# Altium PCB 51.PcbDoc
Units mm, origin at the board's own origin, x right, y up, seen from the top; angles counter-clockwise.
Board outline 100 x 100 mm, 2 copper layers (Top Layer, Bottom Layer); 85 components, 82 nets, 374 pads, 113 vias.
Unrouted connection lines stored in the file: 45.
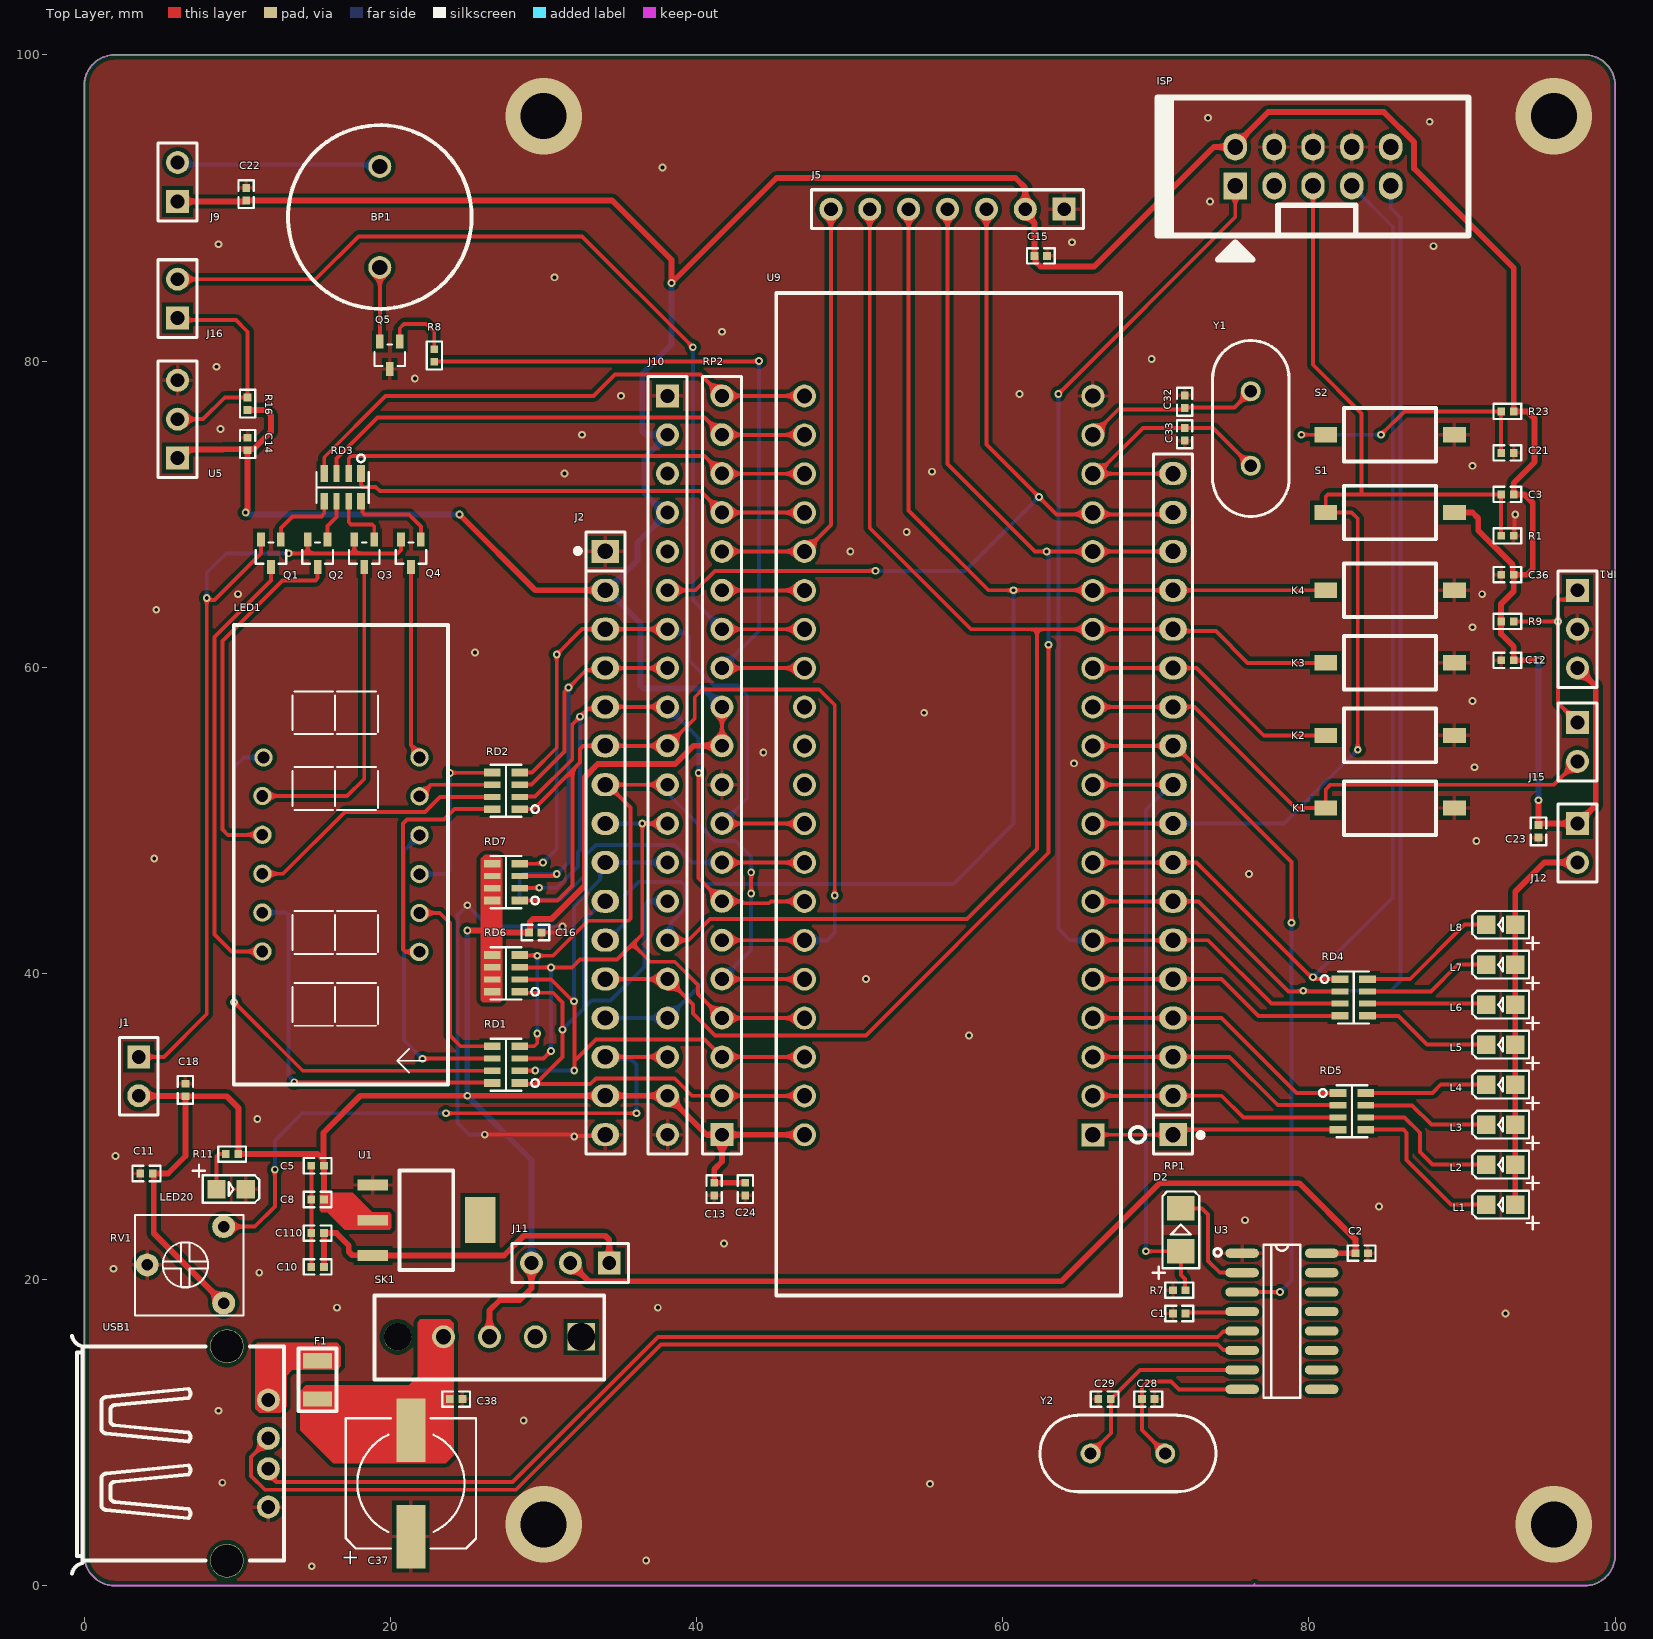
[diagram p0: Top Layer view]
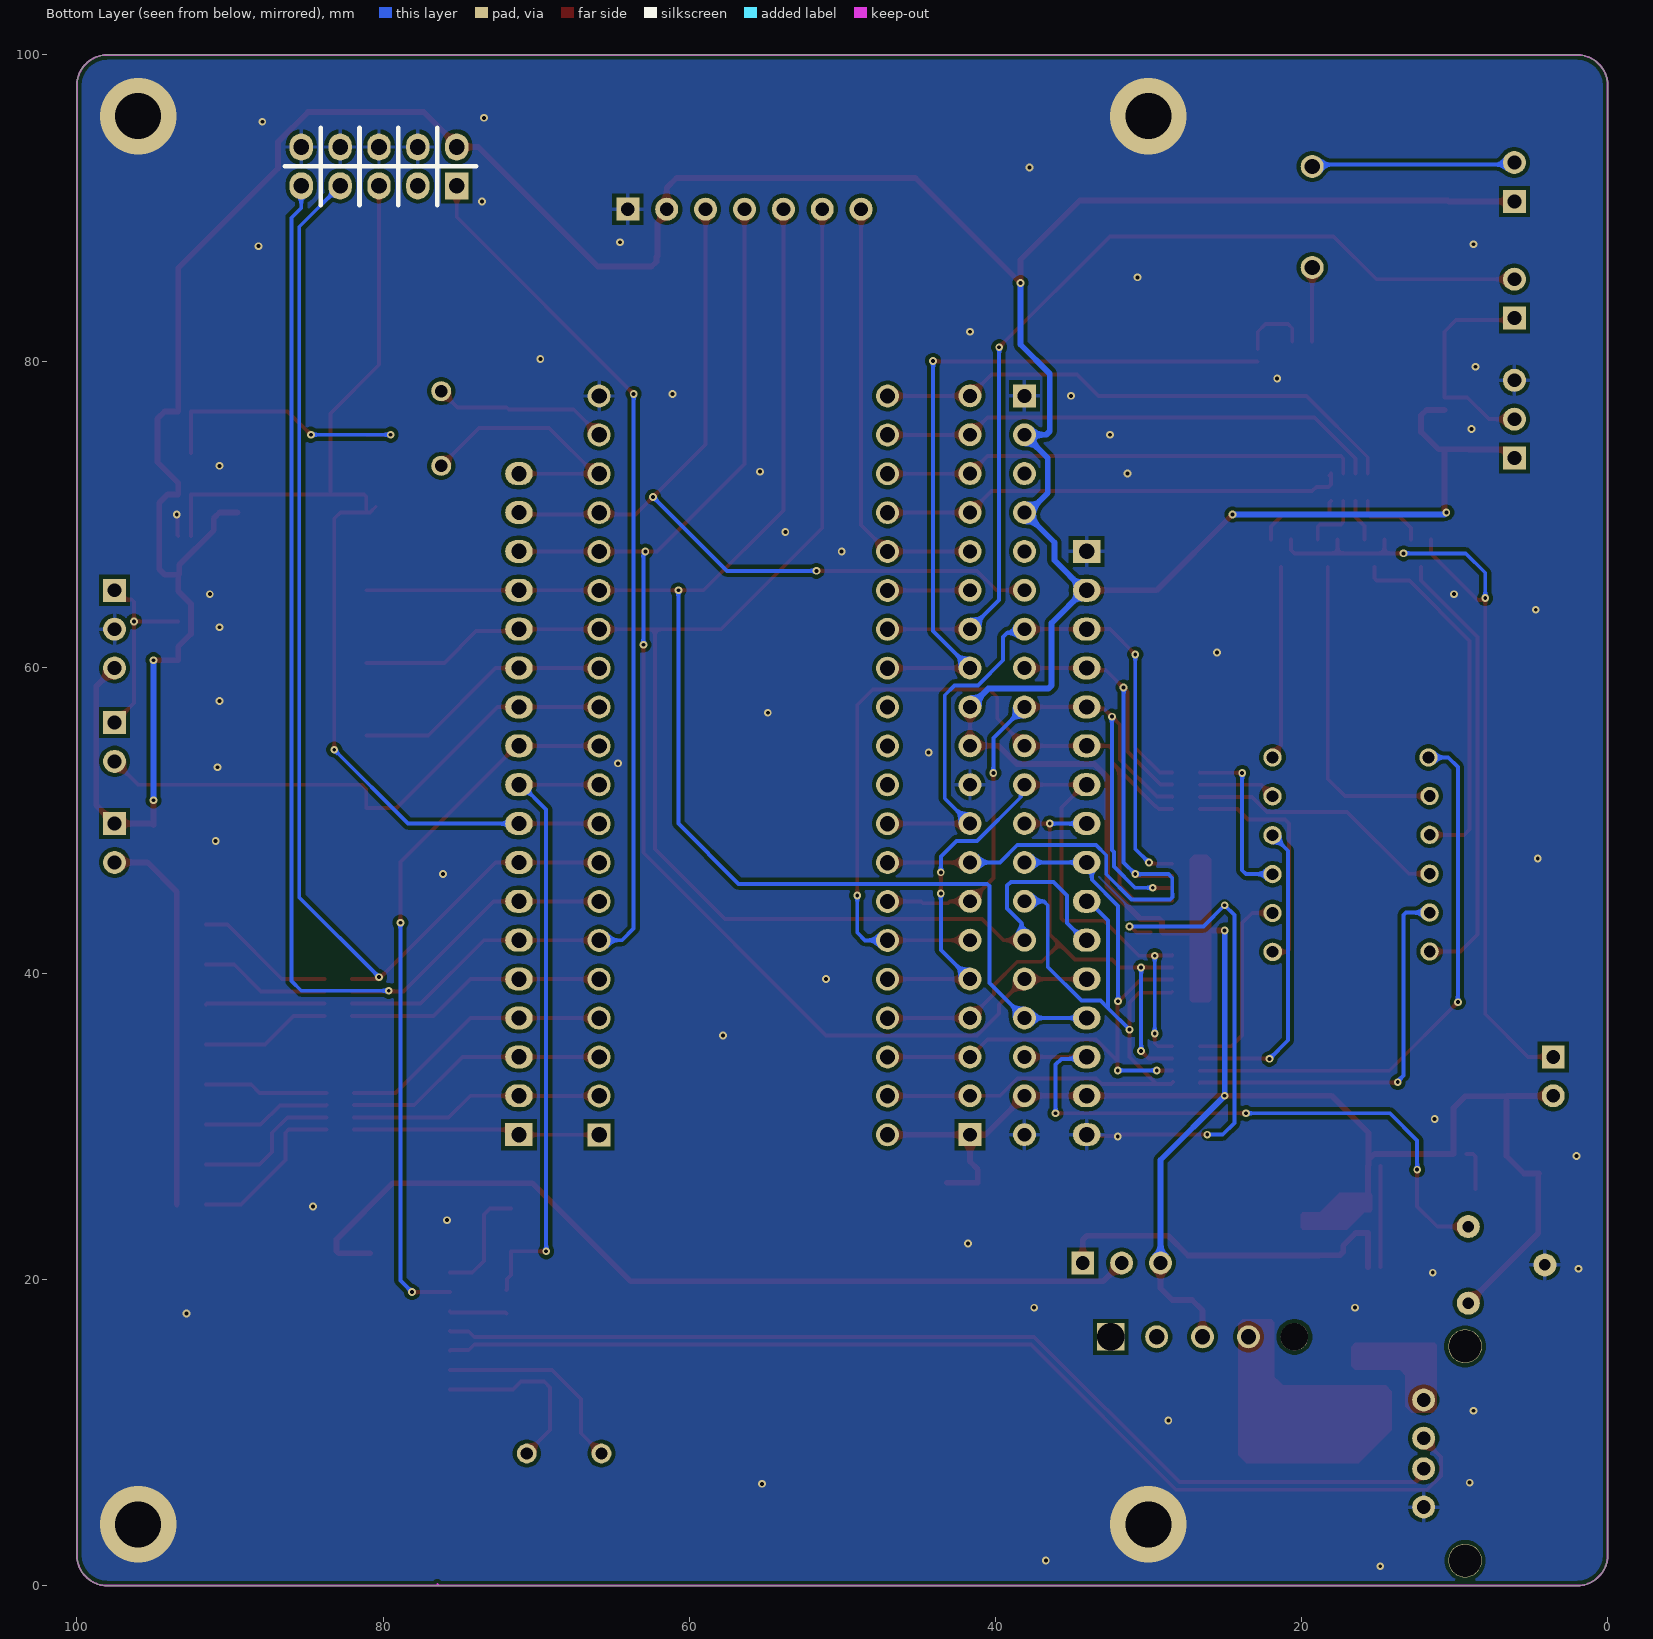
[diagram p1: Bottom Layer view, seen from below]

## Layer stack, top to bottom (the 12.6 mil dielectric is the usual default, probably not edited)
Top Solder: solder mask 0.0102, Solder Resist, Dk 3.5
Top Layer: signal copper 0.0356
Dielectric 1: dielectric 0.32, FR-4, Dk 4.8
Bottom Layer: signal copper 0.0356
Bottom Solder: solder mask 0.0102, Solder Resist, Dk 3.5

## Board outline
2,0 cw(c2,2) 0,2 0,98 cw(c2,98) 2,100 98,100 cw(c98,98) 100,98 100,2 cw(c98,2) 98,0

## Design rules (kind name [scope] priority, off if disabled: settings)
Clearance [All] p1: gap=0.254 ignorepadtopadclearanceinfootprint=FALSE
ComponentClearance [All] p1: gap=0.254 collisioncheckmode=3 verticalgap=100 showdistances=TRUE donotcheckwithout3dbody=TRUE checkcomponentboundary=TRUE
DiffPairsRouting DiffPair_USBDiffPairsRouting [InDifferentialPair ('D_D')] p1: maxlimit=0.254 minlimit=0.254 mostfreqgap=0.254 toplayer_minwidth=0.127 toplayer_maxwidth=0.381 toplayer_prefwidth=0.254 bottomlayer_minwidth=0.127 bottomlayer_maxwidth=0.381 bottomlayer_prefwidth=0.254 maxuncoupledlength=12.7
DiffPairsRouting [All] p2: maxlimit=0.254 minlimit=0.254 mostfreqgap=0.254 toplayer_minwidth=0.381 toplayer_maxwidth=0.381 toplayer_prefwidth=0.381 bottomlayer_minwidth=0.381 bottomlayer_maxwidth=0.381 bottomlayer_prefwidth=0.381 maxuncoupledlength=12.7
Height [All] p1: minheight=-200 maxheight=200 prefheight=26.142
MatchedLengths DiffPair_USBMatchedLengths [InDifferentialPair ('D_D')] p1: tolerance=25.4 checknetsindiffpair=TRUE checkdiffpairvsdiffpair=FALSE checkxsignals=FALSE checkothers=FALSE
MinimumSolderMaskSliver [All] p1: minsoldermaskwidth=0.025
PlaneClearance [All] p1: clearance=0.203
PlaneConnect [All] p1: pad.planeconnectstyle=Relief pad.reliefexpansion=0.508 pad.reliefentries=4 pad.reliefconductorwidth=0.254 pad.reliefairgap=0.254 via.planeconnectstyle=Direct via.reliefexpansion=0.508 via.reliefentries=4 via.reliefconductorwidth=0.254 via.reliefairgap=0.254
PolygonConnect [All] p1: thpad.connectstyle=Relief thpad.reliefconductorwidth=0.254 thpad.reliefentries=4 thpad.polygonreliefangle="90 Angle" thpad.airgapwidth=0.254 smdpad.connectstyle=Relief smdpad.reliefconductorwidth=0.254 smdpad.reliefentries=4 smdpad.polygonreliefangle="90 Angle" smdpad.airgapwidth=0.254 via.connectstyle=Direct via.reliefconductorwidth=0.254 via.reliefentries=4 via.polygonreliefangle="90 Angle" via.airgapwidth=0.254
RoutingVias [All] p1: holewidth=0.254 width=0.508 viastyle="Through Hole" minholewidth=0.254 minwidth=0.508 maxholewidth=0.254 maxwidth=0.508
SilkToSilkClearance [All] p1: silktosilkclearance=0.025
SilkToSolderMaskClearance [IsPad] p1: minsilkscreentomaskgap=0.025 clearancetoexposedcopper=TRUE
SolderMaskExpansion [All] p1: expansion=0.102 istentingtop=FALSE
SupplyNets "Schematic Supply Nets_3" [InNet('GND')] p1: voltage=0.000
SupplyNets "Schematic Supply Nets_2" [InNet('VCC')] p2: voltage=0.000
SupplyNets "Schematic Supply Nets_1" [InNet('VCC_CPU')] p3: voltage=0.000
SupplyNets "Schematic Supply Nets" [InNet('3.3V')] p4: voltage=0.000
Width Width_power [InNetClass('Power')] p1: maxlimit=2.54 minlimit=0.203 preferedwidth=0.381
Width [InNetClass('All Nets')] p2: maxlimit=2.032 minlimit=0.102 preferedwidth=0.254
22 further rules are at their usual default settings.

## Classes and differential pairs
net class Power: 3.3V NetJ12_2 VCC VCC_CPU
differential pair D_D: +D+ -D-

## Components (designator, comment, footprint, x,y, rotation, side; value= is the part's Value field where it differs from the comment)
BP1 "BUZZER" BUZZER 19.304,89.408 r270 top
C1 "104" FPC-0402C 71.53,17.78 r0 top
C2 "104" FPC-0402C 83.439,21.717 r180 top
C3 "105" FPC-0402C 92.964,71.289 r0 top
C5 "220uF/16V" FPC-0402C 15.24,27.432 r0 top
C8 "104" FPC-0402C 15.24,25.231 r0 top
C10 "104" FPC-0402C 15.24,20.828 r0 top
C11 "104" FPC-0402C 4.064,26.924 r0 top
C12 "104" FPC-0402C 92.964,60.452 r0 top
C13 "104" FPC-0402C 41.148,25.908 r90 top
C14 "104" FPC-0402C 10.668,74.578 r270 top
C15 "104" FPC-0402C 62.484,86.868 r180 top
C16 "104" FPC-0402C 29.464,42.672 r180 top
C18 "104" FPC-0402C 6.604,32.385 r270 top
C21 "105" FPC-0402C 92.964,73.999 r180 top
C22 "104" FPC-0402C 10.578,90.902 r270 top
C23 "104" FPC-0402C 94.996,49.276 r90 top
C24 "104" FPC-0402C 43.18,25.908 r90 top
C28 "20P" FPC-0402C 69.498,12.192 r0 top
C29 "20P" FPC-0402C 66.646,12.192 r180 top
C32 "30pF" FPC-0402C 71.882,77.343 r270 top
C33 "30pF" FPC-0402C 71.882,75.213 r90 top
C36 "102" FPC-0402C 92.964,66.04 r0 top
C37 "100uF/16V" FPC-CPCSM-3R2X8R0-1 21.336,6.685 r90 top
C38 "104" FPC-0402C 24.286,12.192 r0 top
C110 "10uF/10V" FPC-0402C 15.24,23.029 r180 top
D2 "1N4148" FPC-1206D 71.628,23.244 r90 top
F1 "FUSE" 1206F 15.24,12.192 r90 top
IR1 "IRRED" HDR1X3 97.536,65.024 r270 top
ISP "ISP" IDE-10 80.264,92.71 r0 top
J1 "2PIN排针" HDR1X2 3.556,34.544 r270 top
J2 "LCD-1602" HDR1X16 34.036,48.514 r270 top
J5 "SIP7" HDR1X7 64.008,89.916 r180 top
J9 "J9" HDR1X2 6.096,90.424 r90 top
J10 "LCD128-64" HDR1X20 38.1,77.724 r270 top
J11 "SIP3" HDR1X3 34.29,21.082 r180 top
J12 "CON2" HDR1X2 97.536,49.784 r270 top
J15 "CON2" HDR1X2 97.536,56.388 r270 top
J16 "CON2" HDR1X2 6.096,82.804 r90 top
K1 "SW-PB" SW-PB 82.296,50.8 r180 top
K2 "SW-PB" SW-PB 82.296,55.541 r180 top
K3 "SW-PB" SW-PB 82.296,60.283 r180 top
K4 "SW-PB" SW-PB 82.296,65.024 r180 top
L1 "LED" FPC-0805D 92.522,24.892 r180 top
L2 "LED" FPC-0805D 92.522,27.505 r180 top
L3 "LED" FPC-0805D 92.522,30.117 r180 top
L4 "LED" FPC-0805D 92.522,32.73 r180 top
L5 "LED" FPC-0805D 92.522,35.342 r180 top
L6 "LED" FPC-0805D 92.522,37.955 r180 top
L7 "LED" FPC-0805D 92.522,40.567 r180 top
L8 "LED" FPC-0805D 92.522,43.18 r180 top
LED1 "4连数码管" CL3641A 16.764,47.752 r90 top
LED20 "RED" FPC-0805D 9.586,25.908 r0 top
Q1 "PNP三极管" FPC-SOT323 12.192,67.448 r180 top
Q2 "PNP三极管" FPC-SOT323 15.24,67.448 r180 top
Q3 "PNP三极管" FPC-SOT323 18.288,67.448 r180 top
Q4 "PNP三极管" FPC-SOT323 21.336,67.448 r180 top
Q5 "PNP三极管" FPC-SOT323 19.954,80.38 r180 top
R1 "10K" FPC-0402R 92.964,68.58 r180 top
R7 "10K" FPC-0402R 71.53,19.304 r0 top
R8 "1K" FPC-0402R 22.86,80.362 r90 top
R9 "5.1K" FPC-0402R 92.964,62.992 r180 top
R11 "1K" FPC-0402R 9.652,28.194 r0 top
R16 "5.1K" FPC-0402R 10.668,77.216 r270 top
R23 "10K" FPC-0402R 92.964,76.708 r0 top
RD1 "100*4" FPC-0603RA 27.548,34.036 r90 top
RD2 "100*4" FPC-0603RA 27.548,51.924 r90 top
RD3 "1k*4" FPC-0603RA 16.872,71.744 r180 top
RD4 "1K*4" FPC-0603RA 82.92,38.424 r270 top
RD5 "1K*4" FPC-0603RA 82.804,30.988 r270 top
RD6 "10K*4" FPC-0603RA 27.548,39.999 r90 top
RD7 "10K*4" FPC-0603RA 27.548,45.961 r90 top
RP1 "18PIN" HDR1X18 71.12,51.054 r90 top
RP2 "20PIN" HDR1X20 41.656,29.464 r90 top
RV1 "10K" RV 6.604,20.955 r90 top
S1 "RST" SW-PB 82.296,70.104 r180 top
S2 "RST" SW-PB 82.296,75.184 r180 top
SK1 "滑动开关" SS-12F44 26.464,16.256 r180 top
U1 "IC_LM1117" SOP-223-3L 22.352,23.876 r270 top
U3 "IC_CH340G" FPC-SO16-150 78.232,17.272 r270 top
U5 "18B20" HDR1X3 6.096,73.66 r90 top
U9 "IC_AT89C5122D-RDRU" DIP40 78.583,26.915 r90 top
USB1 "TYPEC" USB_A 10.668,8.636 r270 top
Y1 "11.0592M" FPC-CO2-5R0X11R5-V 76.2,73.152 r90 top
Y2 "12M" FPC-CO2-5R0X11R5-V 70.612,8.636 r180 top

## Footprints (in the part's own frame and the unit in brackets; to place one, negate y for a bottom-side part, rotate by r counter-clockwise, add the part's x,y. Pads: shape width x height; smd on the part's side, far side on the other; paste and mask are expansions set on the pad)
1206F [mm]
  rect 1x1.9 smd: 1(0,0) 2(2.5,0)
  silkscreen extent -0.8,-1.23 3.3,1.25, body extent -0.33,-0.8 2.87,0.8, height 0.55
BUZZER [mm]
  round 1.5 hole 1: 1(-3.3,0) 2(3.3,0)
  silkscreen extent -6,-6 6,6, body extent -5.87,-5.99 6.13,5.99, height 9
CL3641A [mm]
  round 1.2 hole 0.65: 1(-6.352,-5.101)
  round 1.2 hole 0.762: 1(-6.348,-5.132) 1(-6.348,-5.132) 2(-3.808,-5.132) 3(-1.268,-5.132) 4(1.272,-5.132) 5(3.812,-5.132) 6(6.352,-5.132) 7(6.348,5.059) 8(3.837,5.132) 9(1.297,5.132) 10(-1.243,5.132) 11(-3.783,5.132) 12(-6.323,5.132)
  silkscreen extent -15,-7 15,7, body extent -14.73,-7.25 15.27,6.75, height 2
DIP40 [mm]
  rect 1.5x1.5 hole 1: 1(2.54,12.7)
  round 1.5 hole 1: 2(5.08,12.7) 3(7.62,12.7) 4(10.16,12.7) 5(12.7,12.7) 6(15.24,12.7) 7(17.78,12.7) 8(20.32,12.7) 9(22.86,12.7) 10(25.4,12.7) 11(27.94,12.7) 12(30.48,12.7) 13(33.02,12.7) 14(35.56,12.7) 15(38.1,12.7) 16(40.64,12.7) 17(43.18,12.7) 18(45.72,12.7) 19(48.26,12.7) 20(50.8,12.7) 21(50.8,31.54) 21(50.8,31.54) 22(48.26,31.54) 23(45.72,31.54) 24(43.18,31.54) 25(40.64,31.54) 26(38.1,31.54) 27(35.56,31.54) 28(33.02,31.54) 29(30.48,31.54) 30(27.94,31.54) 31(25.4,31.54) 32(22.86,31.54) 33(20.32,31.54) 34(17.78,31.54) 35(15.24,31.54) 36(12.7,31.54) 37(10.16,31.54) 38(7.62,31.54) 39(5.08,31.54) 40(2.54,31.54)
  silkscreen extent -7.96,9.27 57.54,33.38, body extent -8.11,10.07 57.39,34.13, height 26.14
FPC-0402C [mm]
  rect 0.51x0.51 smd: 1(-0.41,0) 2(0.41,0)
  silkscreen extent -0.91,-0.5 0.91,0.5
FPC-0402R [mm]
  rect 0.51x0.51 smd: 1(-0.41,0) 2(0.41,0)
  silkscreen extent -0.91,-0.5 0.91,0.5
FPC-0603RA [mm]
  rect 0.5x1.1 smd: 1(-1.2,-0.9) 4(1.2,-0.9) 5(1.2,0.9) 8(-1.2,0.9)
  rect 0.4x1.1 smd: 2(-0.4,-0.9) 3(0.4,-0.9) 6(0.4,0.9) 7(-0.4,0.9)
  silkscreen extent -1.7,-2.15 1.7,1
FPC-0805D [mm]
  rect 1.2x1.2 smd: 1(0.95,0) 2(-0.95,0)
  silkscreen extent -2.5,-0.9 1.85,1.6
FPC-1206D [mm]
  rect 1.6x1.8 smd: 1(-1.4,0) 2(1.4,0)
  silkscreen extent -3.2,-1.2 2.5,1.85
FPC-CO2-5R0X11R5-V [mm]
  round 1.3 hole 0.8: 1(0,0) 2(4.88,0)
  silkscreen extent -3.31,-2.5 8.19,2.5
FPC-CPCSM-3R2X8R0-1 [mm]
  rect 4.15x1.9 smd: 1(-3.475,0) 2(3.475,0)
  silkscreen extent -4.25,-4.25 4.25,4.25
FPC-SO16-150 [mm]
  oval 0.6x2.2 smd: 1(-4.445,-2.6) 2(-3.175,-2.6) 3(-1.905,-2.6) 4(-0.635,-2.6) 5(0.635,-2.6) 6(1.905,-2.6) 7(3.175,-2.6) 8(4.445,-2.6) 9(4.445,2.6) 10(3.175,2.6) 11(1.905,2.6) 12(0.635,2.6) 13(-0.635,2.6) 14(-1.905,2.6) 15(-3.175,2.6) 16(-4.445,2.6)
  silkscreen extent -5,-4.45 5,1.2
FPC-SOT323 [mm]
  rect 0.5x0.9 smd: 1(-0.65,-0.9) 2(0.65,-0.9) 3(0,0.9)
  silkscreen extent -1,-0.7 1,0.7
HDR1X2 [mm] "Connector; Header; 2 Position"
  rect 1.5x1.5 hole 0.9: 1(0,0)
  round 1.5 hole 0.9: 2(2.54,0)
  silkscreen extent -1.27,-1.27 3.81,1.27, body extent -1.29,-1.37 3.79,1.17, height 8.43
HDR1X3 [mm] "Connector; Header; 3 Position"
  rect 1.5x1.5 hole 0.9: 1(0,0)
  round 1.5 hole 0.9: 2(2.54,0) 3(5.08,0)
  silkscreen extent -1.27,-1.27 6.35,1.27, body extent -1.27,-1.27 6.35,1.27, height 8
HDR1X7 [mm] "Connector; Header; 7 Position"
  rect 1.5x1.5 hole 0.9: 1(0,0)
  round 1.5 hole 0.9: 2(2.54,0) 3(5.08,0) 4(7.62,0) 5(10.16,0) 6(12.7,0) 7(15.24,0)
  silkscreen extent -1.27,-1.27 16.51,1.27, body extent -1.27,-1.27 16.51,1.27, height 8.54
HDR1X16 [mm] "ZLGLIB"
  rect 1.5x1.8 hole 1: 1(-19.05,0)
  oval 1.5x1.8 hole 1: 2(-16.51,0) 3(-13.97,0) 4(-11.43,0) 5(-8.89,0) 6(-6.35,0) 7(-3.81,0) 8(-1.27,0) 9(1.27,0) 10(3.81,0) 11(6.35,0) 12(8.89,0) 13(11.43,0) 14(13.97,0) 15(16.51,0) 16(19.05,0)
  silkscreen extent -20.32,-1.92 20.32,1.27, body extent -20.32,-1.27 20.32,1.27, height 7.58
HDR1X18 [mm] "ZLGLIB"
  rect 1.5x1.8 hole 1: 1(-21.59,0)
  oval 1.5x1.8 hole 1: 2(-19.05,0) 3(-16.51,0) 4(-13.97,0) 5(-11.43,0) 6(-8.89,0) 7(-6.35,0) 8(-3.81,0) 9(-1.27,0) 10(1.27,0) 11(3.81,0) 12(6.35,0) 13(8.89,0) 14(11.43,0) 15(13.97,0) 16(16.51,0) 17(19.05,0) 18(21.59,0)
  silkscreen extent -22.86,-1.92 22.86,1.27, body extent -22.86,-1.27 22.86,1.27, height 7.58
HDR1X20 [mm] "Connector; Header; 20 Position"
  rect 1.5x1.5 hole 0.9: 1(0,0)
  round 1.5 hole 0.9: 2(2.54,0) 3(5.08,0) 4(7.62,0) 5(10.16,0) 6(12.7,0) 7(15.24,0) 8(17.78,0) 9(20.32,0) 10(22.86,0) 11(25.4,0) 12(27.94,0) 13(30.48,0) 14(33.02,0) 15(35.56,0) 16(38.1,0) 17(40.64,0) 18(43.18,0) 19(45.72,0) 20(48.26,0)
  silkscreen extent -1.27,-1.27 49.53,1.27, body extent -1.34,-1.41 49.46,1.13, height 7.36
IDE-10 [mil] "IDC-10-B,ZLGLIB"
  rect 60x70 hole 40: 1(-200,-50)
  oval 60x70 hole 40: 2(-200,50) 3(-100,-50) 4(-100,50) 5(0,-50) 6(0,50) 7(100,-50) 8(100,50) 9(200,-50) 10(200,50)
  silkscreen extent -400,-240 400,177, body extent -400,-175 400,175, height 394
RV [mm]
  round 1.5 hole 0.762: 1(-2.5,-2.5) 2(0,2.5) 3(2.5,-2.5)
  silkscreen extent -3.3,-3.8 3.26,3.3, body extent -3.2,-3.8 3.2,3.2, height 7.5
SOP-223-3L [mm]
  rect 0.7x2 smd: 1(-2.3,-3.5) 2(0,-3.5) 3(2.3,-3.5)
  rect 3x2 smd: 4(0,3.5)
  silkscreen extent -3.25,-1.75 3.25,1.75, body extent -3.25,-3.63 3.25,3.37, height 0.89
SS-12F44 [mm]
  round 1.5 hole 1: 1(-3,0) 2(0,0) 3(3,0)
  rect 1.8x1.8 hole 1.8: 4(-6,0)
  round 1.8 hole 1.8: 5(6,0)
  silkscreen extent -7.5,-2.71 7.5,2.79, body extent -5.97,-2.88 6.23,2.92, height 11.75
SW-PB [mm]
  rect 1.5x1 smd: 1(-7.2,0) 2(1.2,0)
  silkscreen extent -6,-1.75 0,1.75, body extent -7.03,-1.7 0.97,1.8, height 2.59
USB_A [mm]
  round 1.5 hole 0.9: 1(-3.5,1.355) 2(-1,1.355) 3(1,1.355) 4(3.5,1.355)
  round 2.2 hole 2.1: GND(-7,-1.355) GND(7,-1.355)
  silkscreen extent -7.68,-11.47 7.85,2.37, body extent -7.75,-11.88 8.05,2.22, height 6.35

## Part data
C1 C2 C3 C5 C8 C10 C11 C12 C13 C14 C15 C16 C18 C21 C22 C23 C24 C28 C29 C32 C33 C36 C37 C38: library part CAP
C110: library part CAP1
D2: library part 二极管
IR1 U5: library part SIP3
ISP: library part IC_ISP
J2: library part 16PIN
J9 J12 J15 J16: library part 2PIN排针
J10: library part 20PIN
K1 K2 K3 K4 S1 S2: library part KEY
LED20: library part LED
R1 R7 R8 R9 R11 R16 R23: library part res1
RD1 RD2 RD3 RD4 RD5 RD6 RD7: library part RP
RV1: library part VR
USB1: library part USB座
Y1 Y2: library part XT

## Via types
v1: diameter 0.508, hole 0.254, Top Layer to Bottom Layer, 109 vias
v2: diameter 5, hole 3, Top Layer to Bottom Layer, 4 vias

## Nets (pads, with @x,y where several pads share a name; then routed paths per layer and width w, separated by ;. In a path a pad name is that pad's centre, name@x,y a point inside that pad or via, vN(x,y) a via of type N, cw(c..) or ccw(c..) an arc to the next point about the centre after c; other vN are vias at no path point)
3.3V: C10.2 C110.1 J11.1 U1.3 | length 23.8
  Top Layer w0.381: C10.2 C110.1 16.468,23.029 17.272,22.225 17.272,21.813 17.495,21.59 18.838,21.59 U1.3 27.418,21.576 28.702,22.86 34.036,22.86 34.29,22.606 J11.1
COM1: LED1.12 Q1.3 | length 29.1
  Top Layer w0.254: LED1.12 9.625,41.429 8.509,42.545 8.509,61.976 12.192,65.659 Q1.3
COM2: LED1.9 Q2.3 | length 23.7
  Top Layer w0.254: LED1.9 9.371,49.049 9.017,49.403 9.017,61.722 12.954,65.659 15.091,65.659 15.24,65.808 Q2.3
COM3: LED1.8 Q3.3 | length 21
  Top Layer w0.254: LED1.8 17.172,51.589 18.288,52.705 Q3.3
COM4: LED1.6 Q4.3 | length 12.7
  Top Layer w0.254: Q4.3 21.336,54.92 21.896,54.36 LED1.6
D0: J2.10 J10.14 RD1.1 RD6.1 RP2.2 U9.39 | length 48.8
  Top Layer w0.254: RD1.1@28.391,32.893 28.518,32.766 29.464,32.766 ; RD6.1 28.512,38.735 30.607,38.735 31.242,38.1 v1(31.242,36.322) 31.242,34.544 29.464,32.766 ; U9.39 47.039,31.999 41.661,31.999 RP2.2 39.699,32.004 38.568,33.135 33.418,33.135 33.049,32.766 29.464,32.766
  Bottom Layer w0.254: v1(31.242,36.322) 32.639,37.719 ; J2.10 33.886,44.704 32.639,43.457 32.639,37.719 ; J10.14 36.83,44.704 36.576,44.45 36.576,40.415 34.376,38.215 33.135,38.215 32.639,37.719
D1: J2.9 J10.13 RD1.2 RD6.2 RP2.3 U9.38 | length 42.3
  Top Layer w0.254: RD1.2 28.46,33.648 29.448,33.648 v1(29.459,33.66) ; RD6.2 30.505,39.599 v1@32.004,38.1 ; v1(31.984,38.179) 32.032,38.13 32.032,37.951 v1@32.033,33.684 ; v1(32.004,33.655) v1@32.015,33.666 ; 32.058,34.315 33.418,35.675 40.525,35.675 RP2.3 41.661,34.539 47.039,34.539 U9.38
  Bottom Layer w0.254: v1(29.459,33.66) 29.462,33.657 32.002,33.657 v1(32.004,33.655) ; v1(31.984,38.179) 31.984,44.401 33.696,46.113 33.696,46.904 J2.9 J10.13
D2: J2.8 J10.12 RD1.3 RD6.3 RP2.4 U9.37 | length 41.5
  Top Layer w0.254: RD1.3 29.991,34.436 v1(30.48,34.925) ; RD6.3 28.454,40.392 30.474,40.392 v1(30.48,40.386) 31.877,40.386 32.385,40.894 34.798,40.894 35.814,41.91 ; J10.12 v1(36.449,49.784) 36.449,42.545 35.814,41.91 ; U9.37 47.039,37.079 41.661,37.079 RP2.4 40.095,38.645 40.095,39.228 38.568,40.755 36.969,40.755 35.814,41.91
  Bottom Layer w0.254: v1(30.48,34.925) v1(30.48,40.386) ; J2.8 v1(36.449,49.784)
D3: J2.7 J10.11 RD1.4 RD6.4 RP2.5 U9.36 | length 50.6
  Top Layer w0.254: RD1.4 29.394,35.236 29.591,35.433 v1(29.591,36.068) ; RD6.4 28.473,41.173 29.566,41.173 v1(29.591,41.148) 30.607,41.148 32.893,43.434 35.538,43.434 35.687,43.583 35.687,50.823 J2.7@34.186,52.324 ; J2.7 J2.7@34.186,52.324 ; J10.11 J2.7@34.186,52.324 ; RP2.5 41.661,39.619 47.039,39.619 U9.36 ; v1(43.561,45.212) v1(43.561,46.6)
  Bottom Layer w0.254: v1(29.591,36.068) v1(29.591,41.148) ; J10.11 38.338,52.086 38.338,51.502 41.188,48.653 42.533,48.653 43.191,47.995 43.556,47.63 43.556,46.605 v1(43.561,46.6) ; RP2.5 43.561,41.529 v1(43.561,45.212)
D4: J2.6 J10.10 RD2.1 RD7.1 RP2.6 U9.35 | length 59.4
  Top Layer w0.254: RD7.1 30.918,44.761 31.899,45.742 31.899,53.278 ; RD2.1 29.31,50.724 29.529,50.943 29.563,50.943 31.899,53.278 ; RP2.6 41.661,42.159 47.039,42.159 U9.35 ; v1(49.022,45.085) 49.022,57.531 48.006,58.547 40.386,58.547 39.878,58.039 39.878,56.642 J10.10 J2.6 32.588,54.864 32.385,54.661 32.385,53.765 31.899,53.278
  Bottom Layer w0.254: U9.35 48.505,42.155 49.022,42.672 v1(49.022,45.085)
D5: J2.5 J10.9 RD2.2 RD7.2 RP2.7 U9.34 | length 47.3
  Top Layer w0.254: RD7.2 28.464,45.577 29.702,45.577 v1(29.718,45.593) ; RD2.2 28.464,51.54 29.442,51.54 31.877,53.975 31.877,56.261 v1(32.385,56.769) 32.893,57.277 33.909,57.277 J2.5 J10.9 ; v1(40.132,53.086) 40.132,46.228 41.661,44.699 42.967,44.699 43.089,44.577 44.717,44.577 44.839,44.699 47.039,44.699 U9.34
  Bottom Layer w0.254: v1(29.718,45.593) 30.87,45.593 32.247,46.97 32.247,47.923 32.385,48.061 v1(32.385,56.769) ; J10.9 40.132,55.372 v1(40.132,53.086)
D6: J2.4 J10.8 RD2.3 RD7.3 RP2.8 U9.33 | length 55.2
  Top Layer w0.254: RD7.3 30.672,46.361 30.792,46.482 v1(30.861,46.482) ; RD2.3 28.457,52.333 29.219,52.333 31.369,54.483 31.369,58.387 32.788,59.806 33.898,59.806 J2.4 J10.8 ; RP2.8@41.665,47.235 U9.33
  Bottom Layer w0.254: v1(31.623,58.674) 31.623,47.244 v1(30.861,46.482) 28.702,46.482 28.448,46.228 28.448,45.212 28.426,45.19 28.426,44.98 28.575,44.831 31.115,44.831 32.755,46.471 32.755,47.712 33.418,48.375 38.568,48.375 39.699,47.244 RP2.8
D7: J2.3 J10.7 RD2.4 RD7.4 RP2.9 U9.32 | length 55
  Top Layer w0.254: RD7.4 29.889,47.161 v1(29.972,47.244) ; RD2.4 29.248,53.124 30.861,54.737 v1(30.861,60.833) 32.512,62.484 J2.3 J10.7 ; RP2.9 41.661,49.779 47.039,49.779 U9.32
  Bottom Layer w0.254: v1(29.972,47.244) 30.861,48.133 v1(30.861,60.833) ; J10.7 38.338,62.246 39.227,62.246 39.497,61.976 39.497,60.452 41.136,58.813 42.66,58.813 43.307,58.166 43.307,51.435 RP2.9
D+: U3.5 USB1.3 | length 68.2
  Top Layer w0.254: USB1.3 12.023,7.303 12.551,6.775 27.982,6.775 37.463,16.256 74.041,16.256 74.399,16.614 75.609,16.614 U3.5
D-: U3.6 USB1.2 | length 72.1
  Top Layer w0.254: USB1.2 12.023,9.533 10.892,8.402 10.892,7.168 11.793,6.267 28.193,6.267 37.674,15.748 74.041,15.748 74.399,15.39 75.609,15.39 U3.6
DB1: RD5.4 RP1.1 U9.1 | length 16.2
  Top Layer w0.254: U9.1 71.111,29.455 71.444,29.788 RD5.4
DB2: RD5.3 RP1.2 U9.2 | length 16.6
  Top Layer w0.254: U9.2 65.888,31.999 71.115,31.999 RP1.2 74.295,32.004 75.711,30.588 RD5.3
DB3: RD5.2 RP1.3 U9.3 | length 17.3
  Top Layer w0.254: U9.3 65.888,34.539 71.115,34.539 RP1.3 74.803,34.544 77.959,31.388 RD5.2
DB4: RD5.1 RP1.4 U9.4 | length 18.1
  Top Layer w0.254: U9.4 65.888,37.079 71.115,37.079 RP1.4 74.295,37.084 79.191,32.188 RD5.1
DB5: RD4.4 RP1.5 U9.5 | length 17.1
  Top Layer w0.254: U9.5 65.888,39.619 71.115,39.619 RP1.5 74.295,39.624 76.695,37.224 RD4.4
DB6: ISP.1 RD4.3 RP1.6 U9.6 | length 73.7
  Top Layer w0.254: v1(63.627,77.851) 75.184,89.408 ISP.1 ; U9.6 65.888,42.159 71.115,42.159 RP1.6 73.406,42.164 77.546,38.024 RD4.3
  Bottom Layer w0.254: v1(63.627,77.851) 63.627,42.926 64.389,42.164 65.874,42.164 U9.6
DB7: ISP.9 RD4.2 RP1.7 U9.7 | length 77.4
  Top Layer w0.254: U9.7 65.888,44.699 71.115,44.699 RP1.7 72.771,44.704 78.651,38.824 RD4.2
  Bottom Layer w0.254: v1(79.629,38.862) 85.344,38.862 85.979,39.497 85.979,89.36 85.344,89.995 ISP.9
DB8: ISP.7 RD4.1 RP1.8 U9.8 | length 74.2
  Top Layer w0.254: U9.8 65.888,47.239 71.115,47.239 RP1.8 72.644,47.244 80.264,39.624 RD4.1
  Bottom Layer w0.254: v1(80.264,39.751) 85.471,44.958 85.471,88.773 ISP.7
GND: C1.1 C2.1 C11.1 C12.1 C13.1 C14.1 C15.1 C16.1 C18.1 C21.1 C22.1 C23.1 C24.1 C28.2 C29.2 C32.1 C33.1 C36.1 C37.1 C38.2 IR1.2 ISP.4 ISP.6 ISP.8 ISP.10 J2.1 J2.16 J5.1 J10.1 J10.20 K1.1 K2.1 K3.1 K4.1 LED20.1 Q5.3 R1.1 R7.1 RP2.10 RV1.2 S2.1 U1.1 U3.1 U5.3 U9.20 USB1.4 | length 34.3
  Top Layer w0.254: v1(26.162,29.464) 31.808,29.464 31.935,29.337 v1(32.004,29.337) 32.053,29.386 33.958,29.386 J2.16 ; C16.1 30.792,42.672 31.173,43.053 v1(31.242,43.053) ; R1.1 93.423,68.629 93.423,69.928 v1(93.472,69.977)
  Bottom Layer w0.254: v1(26.162,29.464) 25.146,29.464 24.384,30.226 24.384,43.815 v1(25.019,44.45) 26.416,43.053 v1(31.242,43.053)
  other v1: 14.859,1.27 36.703,1.651 55.246,6.656 9.017,6.731 28.702,10.795 8.763,11.43 92.837,17.78 16.51,18.161 37.465,18.161 11.43,20.447 1.905,20.701 41.783,22.352 75.819,23.876 84.582,24.765 2.032,28.067 11.303,30.48 57.785,35.941 51.054,39.624 76.073,46.482 4.572,47.498 90.932,48.641 90.805,53.467 64.643,53.721 44.356,54.431 54.864,57.023 90.678,57.785 25.527,60.96 90.678,62.611 4.699,63.754 10.033,64.77 91.313,64.77 50.038,67.564 53.721,68.834 31.369,72.644 55.372,72.771 90.678,73.152 32.512,75.184 8.89,75.565 35.052,77.724 61.087,77.851 21.59,78.867 8.636,79.629 69.723,80.137 41.656,81.915 30.709,85.465 88.138,87.503 8.763,87.63 64.516,87.757 73.533,90.424 37.761,92.648 87.884,95.631 73.406,95.885
  other v2: 30,4 96,4 30,96 96,96
INT1: K2.2 RP1.13 U9.13 | length 17
  Top Layer w0.254: U9.13 65.888,59.939 71.115,59.939 RP1.13 72.644,59.944 77.047,55.541 K2.2
IR: J15.2 K1.2 RP1.12 U9.12 | length 36.4
  Top Layer w0.254: U9.12 65.888,57.399 71.115,57.399 RP1.12 72.517,57.404 79.121,50.8 K1.2 81.096,52.013 81.407,52.324 96.012,52.324 J15.2
LCDEN: J2.11 J5.6 J10.15 K3.2 RP1.14 U9.14 | length 107.2
  Top Layer w0.254: J10.15 39.475,42.164 40.872,43.561 57.658,43.561 62.23,48.133 62.23,62.475 ; J5.6 51.308,69.088 57.921,62.475 62.23,62.475 ; K3.2 75.988,60.283 73.914,62.357 71.247,62.357 RP1.14 71.115,62.479 65.888,62.479 U9.14 62.23,62.475
  Bottom Layer w0.254: J2.11 34.186,42.164 35.317,43.295 35.317,45.096 36.195,45.974 38.989,45.974 39.231,45.732 39.231,44.236 38.29,43.295 38.29,42.354 J10.15
NetBP1_1: BP1.1 J9.2 | length 13.3
  Bottom Layer w0.254: J9.2 6.224,92.836 19.176,92.836 BP1.1
NetBP1_2: BP1.2 Q5.2 | length 4.8
  Top Layer w0.254: Q5.2 BP1.2
NetC5_1: C5.1 C8.1 C10.1 C110.2 | length 6.6
  Top Layer w0.254: C10.1 C5.1
NetC21_2: C21.2 R23.1 S2.2 | length 18
  Top Layer w0.254: v1(79.502,75.184) S2.2 ; v1(84.709,75.184) 86.233,76.708 R23.1 C21.2
  Bottom Layer w0.254: v1(79.502,75.184) v1(84.709,75.184)
NetC37_2: C37.2 C38.1 F1.1 SK1.3
NetD2_2: D2.2 U3.2 | length 7.5
  Top Layer w0.254: D2.2 73.019,24.644 73.406,24.257 73.406,21.209 74.168,20.447 U3.2
NetF1_2: F1.2 USB1.1
NetIR1_1: IR1.1 J15.1 R9.1 | length 12.9
  Top Layer w0.254: R9.1 v1(96.266,62.992) ; J15.1 96.266,57.658 v1(96.266,62.992) ; IR1.1 96.923,64.411 96.415,64.411 96.266,64.262 v1(96.266,62.992)
NetJ1_1: J1.1 Q1.2 Q2.2 Q3.2 Q4.2 | length 55.8
  Top Layer w0.254: J1.1 5.207,34.544 8.001,37.338 v1(8.001,64.516) ; v1@8.128,64.389 8.509,64.389 11.542,67.422 Q1.2 ; v1(13.335,67.437) 14.59,67.437 ; Q2.2 14.59,67.437 ; Q3.2 17.638,67.437 ; Q4.2 20.676,68.338 20.676,67.666 20.447,67.437 17.638,67.437 ; 14.59,67.437 17.638,67.437
  Bottom Layer w0.254: v1(8.001,64.516) 8.001,66.167 9.271,67.437 v1(13.335,67.437)
NetJ2_14: J2.14 J10.18 RV1.3 | length 42
  Top Layer w0.254: RV1.3 11.136,23.455 12.446,24.765 v1(12.446,27.178) ; v1(23.622,30.861) v1(36.068,30.861) ; J2.14 J10.18
  Bottom Layer w0.254: v1(12.446,27.178) 12.446,29.083 14.224,30.861 v1(23.622,30.861) ; J2.14 34.163,34.417 35.687,34.417 36.068,34.036 v1(36.068,30.861)
NetJ12_2: J12.2 L1.2 L2.2 L3.2 L4.2 L5.2 L6.2 L7.2 L8.2 | length 25.3
  Top Layer w0.381: L1.2 93.472,45.339 95.377,47.244 J12.2
NetJ16_1: J16.1 R16.1 U5.2 | length 14.4
  Top Layer w0.254: U5.2 7.747,76.2 9.173,77.626 R16.1 10.668,81.915 9.906,82.677 6.223,82.677 J16.1
NetL1_1: L1.1 RD5.5 | length 10.9
  Top Layer w0.254: RD5.5 86.163,29.788 86.36,29.591 86.36,27.813 89.281,24.892 L1.1
NetL2_1: L2.1 RD5.6 | length 9.9
  Top Layer w0.254: RD5.6 86.252,30.588 87.249,29.591 87.249,28.321 88.065,27.505 L2.1
NetL3_1: L3.1 RD5.7 | length 8.4
  Top Layer w0.254: RD5.7 83.723,31.369 86.741,31.369 87.993,30.117 L3.1
NetL4_1: L4.1 RD5.8 | length 8.1
  Top Layer w0.254: RD5.8 88.068,32.188 88.61,32.73 L4.1
NetL5_1: L5.1 RD4.5 | length 8.5
  Top Layer w0.254: RD4.5 85.839,37.224 87.721,35.342 L5.1
NetL6_1: L6.1 RD4.6 | length 7.8
  Top Layer w0.254: RD4.6 91.503,38.024 L6.1
NetL7_1: L7.1 RD4.7 | length 8.5
  Top Layer w0.254: RD4.7 87.973,38.824 89.716,40.567 L7.1
NetL8_1: L8.1 RD4.8 | length 9.2
  Top Layer w0.254: RD4.8 86.614,39.624 90.17,43.18 L8.1
NetLED1_1: LED1.1 RD2.8 | length 15.5
  Top Layer w0.254: LED1.1@21.865,41.4 21.864,41.402 20.977,41.402 20.828,41.551 20.828,49.784 21.082,50.038 23.495,50.038 24.181,50.724 RD2.8
NetLED1_2: LED1.2 RD1.5 | length 12.7
  Top Layer w0.254: LED1.2 23.218,43.944 23.876,43.285 23.876,35.941 24.581,35.236 RD1.5
NetLED1_3: LED1.3 RD2.5 | length 11.2
  Top Layer w0.254: v1(23.876,53.086) 23.895,53.105 26.629,53.105 RD2.5
  Bottom Layer w0.254: LED1.3 23.624,46.484 23.876,46.736 v1(23.876,53.086)
NetLED1_4: LED1.4 RD1.6 | length 20.1
  Top Layer w0.254: v1(22.098,34.417) 22.107,34.426 26.638,34.426 RD1.6
  Bottom Layer w0.254: LED1.4 20.884,48.011 20.884,35.631 v1(22.098,34.417)
NetLED1_5: LED1.5 RD2.6 | length 5.1
  Top Layer w0.254: LED1.5 22.657,52.324 RD2.6
NetLED1_7: LED1.7 RD1.7 | length 36.3
  Top Layer w0.254: v1(9.785,38.118) 14.268,33.636 RD1.7
  Bottom Layer w0.254: v1(9.785,38.118) 9.785,53.473 10.414,54.102 11.704,54.102 LED1.7
NetLED1_10: LED1.10 RD2.7 | length 17.1
  Top Layer w0.254: LED1.10 12.981,46.509 17.018,50.546 22.266,50.546 23.244,51.524 RD2.7
NetLED1_11: LED1.11 RD1.8 | length 25.8
  Top Layer w0.254: v1(13.716,32.893) 13.744,32.865 26.619,32.865 RD1.8
  Bottom Layer w0.254: LED1.11 13.186,43.969 13.335,43.82 13.335,33.34 13.716,32.959 v1(13.716,32.893)
NetLED20_2: LED20.2 R11.1 | length 2.8
  Top Layer w0.254: LED20.2 8.636,28.045 8.785,28.194 R11.1
NetQ1_1: Q1.1 RD3.5 | length 4.8
  Top Layer w0.254: Q1.1 12.842,69.103 13.589,69.85 15.494,69.85 15.672,70.028 RD3.5
NetQ2_1: Q2.1 RD3.6 | length 2.7
  Top Layer w0.254: Q2.1 15.89,69.23 16.472,69.812 RD3.6
NetQ3_1: Q3.1 RD3.7 | length 4
  Top Layer w0.254: RD3.7 17.272,69.476 17.421,69.327 18.789,69.327 18.938,69.178 Q3.1
NetQ4_1: Q4.1 RD3.8 | length 5.8
  Top Layer w0.254: RD3.8 18.161,70.755 18.161,70.126 18.31,69.977 21.209,69.977 21.986,69.2 Q4.1
NetQ5_1: Q5.1 R8.2 | length 4.6
  Top Layer w0.254: Q5.1 20.604,82.139 20.888,82.423 22.352,82.423 22.86,81.915 R8.2
P3.0: D2.1 R7.2 RP1.10 U9.10 | length 41.5
  Top Layer w0.254: U9.10 65.888,52.319 71.115,52.319 RP1.10 ; v1(69.342,21.844) D2.1 71.628,20.303 71.893,20.038 71.893,19.351 R7.2
  Bottom Layer w0.254: v1(69.342,21.844) 69.342,50.696 70.97,52.324 RP1.10
P3.1: RP1.11 U3.3 U9.11 | length 47
  Top Layer w0.254: U9.11 65.888,54.859 71.115,54.859 RP1.11 71.27,54.864 78.867,47.267 v1(78.867,43.307) ; U3.3 v1(78.105,19.177)
  Bottom Layer w0.254: v1(78.105,19.177) 78.867,19.939 v1(78.867,43.307)
P20: RD3.4 RP2.20 U9.21 | length 35.3
  Top Layer w0.254: RD3.4 15.672,73.711 19.685,77.724 33.274,77.724 34.671,79.121 40.259,79.121 RP2.20 41.661,77.719 47.039,77.719 U9.21@47.043,77.715
P21: RD3.3 RP2.19 U9.22 | length 33.1
  Top Layer w0.254: RD3.3 16.472,73.622 19.165,76.315 40.525,76.315 RP2.19 41.661,75.179 47.039,75.179 U9.22
P22: RD3.2 RP2.18 U9.23 | length 31.3
  Top Layer w0.254: RD3.2 17.272,73.638 17.421,73.787 40.513,73.787 RP2.18 41.661,72.639 47.039,72.639 U9.23
P23: RD3.1 RP2.17 U9.24 | length 30.6
  Top Layer w0.254: RD3.1@18.183,72.533 RD3.1 18.072,71.924 18.221,71.775 19.03,71.775 19.304,71.501 40.259,71.501 RP2.17 41.661,70.099 47.039,70.099 U9.24
P24: J5.7 RP2.16 U9.25 | length 28.5
  Top Layer w0.254: RP2.16 41.661,67.559 47.039,67.559 U9.25 48.768,69.28 J5.7
P25: RP2.15 U9.26 | length 5.4
  Top Layer w0.254: RP2.15 41.661,65.019 47.039,65.019 U9.26
P26: J16.2 RP2.14 U9.27 | length 62.4
  Top Layer w0.254: J16.2 15.113,85.344 17.907,88.138 32.512,88.138 v1(39.751,80.899) ; RP2.14 41.661,62.479 47.039,62.479 U9.27
  Bottom Layer w0.254: v1(39.751,80.899) 39.751,64.389 RP2.14
P27: R8.1 RP2.13 U9.28 | length 47.7
  Top Layer w0.254: R8.1 22.889,79.981 44.04,79.981 v1(44.069,80.01) ; RP2.13 41.661,59.939 47.039,59.939 U9.28
  Bottom Layer w0.254: RP2.13 44.069,62.357 v1(44.069,80.01)
RD: J5.3 J10.6 RP1.17 U9.17 | length 56.3
  Top Layer w0.254: J10.6 39.92,65.024 41.19,66.294 v1(51.689,66.294) ; J5.3 58.928,74.549 v1(62.357,71.12) 63.5,69.977 70.993,69.977 RP1.17
  Bottom Layer w0.254: v1(51.689,66.294) 57.531,66.294 v1(62.357,71.12)
REST: C3.1 ISP.5 R1.2 RP1.9 S1.2 U9.9 | length 74.6
  Top Layer w0.254: U9.9 65.888,49.779 71.115,49.779 RP1.9 ; ISP.5@80.264,90.969 ISP.5 80.264,79.756 83.439,76.581 83.439,71.317 ; S1.2@80.473,70.477 80.846,70.104 S1.2 ; v1(83.185,54.61) 83.185,69.701 82.782,70.104 S1.2 ; R1.2 C3.1 81.245,71.289 81.096,71.141 S1.2
  Bottom Layer w0.254: RP1.9 78.359,49.784 v1(83.185,54.61)
RS: J2.13 J5.5 J10.17 K4.2 RP1.15 U9.15 | length 100
  Top Layer w0.254: J5.5 53.848,70.231 59.055,65.024 v1(60.706,65.024) RP1.15 K4.2
  Bottom Layer w0.254: J2.13 J10.17 40.386,39.37 40.386,45.698 40.535,45.847 56.769,45.847 60.706,49.784 v1(60.706,65.024)
V3: C1.2 U3.4 | length 3.7
  Top Layer w0.254: C1.2 72.003,17.843 75.569,17.843 U3.4
VCC: C3.2 C5.2 C8.2 C11.2 C12.2 C13.2 C14.2 C15.2 C16.2 C18.2 C22.2 C23.2 C24.2 C36.2 IR1.3 ISP.2 J1.2 J2.2 J2.15 J5.2 J9.1 J10.2 J10.4 J10.19 J11.3 J12.1 R9.2 R11.2 R16.2 R23.2 RD6.5 RD6.6 RD6.7 RD6.8 RD7.5 RD7.6 RD7.7 RD7.8 RP2.1 RP2.11 RP2.12 RV1.1 S1.1 SK1.2 U1.2 U5.1 U9.40 | length 382.1
  Top Layer w0.254: RP2.11 RP2.12
  Top Layer w0.381: J1.2 3.571,31.989 6.589,31.989 C18.2 9.3,31.975 10.062,31.213 R11.2 15.24,28.194 15.621,27.813 ; U5.1 6.656,74.22 9.069,74.22 9.082,74.233 10.603,74.233 C14.2 ; J9.1 10.38,90.424 10.443,90.486 34.482,90.486 38.354,86.614 v1(38.354,85.09) 45.212,91.948 60.833,91.948 61.468,91.313 J5.2 61.468,89.613 62.074,89.007 C15.2 62.138,86.803 62.138,86.485 62.455,86.168 65.975,86.168 73.787,93.98 ISP.2 75.184,94.107 77.343,96.266 84.891,96.266 86.868,94.289 86.868,92.583 93.374,86.077 R23.2 94.265,76.708 94.742,76.231 94.742,73.406 93.374,72.038 C3.2 94.065,71.289 94.615,70.739 94.615,66.39 94.265,66.04 C36.2 ; 6.604,31.692 6.604,28.067 5.461,26.924 C11.2 4.539,26.859 4.539,23.02 RV1.1 ; v1(10.541,70.104) 10.541,70.138 10.668,70.265 C14.2 ; R16.2 11.84,76.806 12.192,76.454 12.192,75.373 11.051,74.233 10.733,74.233 C14.2 ; C8.2 C5.2 15.621,27.461 15.621,27.813 ; v1(24.511,69.977) 29.464,65.024 J2.2 ; v1(25.019,42.799) 26.543,42.799 26.67,42.672 C16.2 29.118,42.737 29.118,43.373 29.306,43.561 30.526,43.561 32.691,45.726 32.691,52.819 33.542,53.669 38.595,53.669 39.789,54.864 RP2.11 ; SK1.2 26.464,17.986 27.147,18.669 28.448,18.669 29.21,19.431 J11.3 ; C24.2 C13.2 41.148,27.195 41.656,27.703 RP2.1 ; U9.40 41.665,29.455 RP2.1 ; S1.1 90.678,70.104 91.059,69.723 91.059,68.936 93.31,66.686 93.31,66.105 C36.2 ; v1(94.996,51.308) C23.2 95.094,49.784 J12.1 98.731,50.979 98.731,58.749 IR1.3 ; v1(94.996,60.452) C12.2 93.374,61.344 92.554,62.164 R9.2 92.554,64.138 93.374,64.958 C36.2 ; 15.621,27.813 15.621,29.591 18.034,32.004 v1(25.019,32.004) J2.15 J10.19 40.64,29.464 RP2.1
  Bottom Layer w0.381: v1(10.541,70.104) 10.668,69.977 v1(24.511,69.977) ; v1(25.019,42.799) v1(25.019,32.004) 29.21,27.813 J11.3 ; v1(38.354,85.09) 38.354,81.072 36.449,79.167 36.449,75.407 36.672,75.184 J10.2 36.576,73.66 36.576,71.374 37.846,70.104 J10.4 36.143,68.147 36.143,66.981 34.186,65.024 36.322,62.888 36.322,58.822 36.545,58.599 40.461,58.599 RP2.12 ; v1(94.996,51.308) v1(94.996,60.452)
VCC_CPU: C2.2 J11.2 U3.16 | length 59
  Top Layer w0.381: J11.2 32.945,19.887 63.829,19.887 70.231,26.289 79.375,26.289 83.029,22.635 83.029,21.844 82.902,21.717 U3.16
WR: J2.12 J5.4 J10.16 RP1.16 U9.16 | length 89.2
  Top Layer w0.254: J2.12 J10.16 39.763,37.961 39.763,37.378 41.197,35.944 51.057,35.944 62.992,47.879 v1(62.992,61.468) ; J5.4 56.388,73.279 62.112,67.555 U9.16 65.888,67.559 71.115,67.559 RP1.16
  Bottom Layer w0.254: v1(62.865,67.564) 62.865,67.495 62.992,67.368 v1(62.992,61.468)
X1: C32.2 U9.19 Y1.2 | length 11.4
  Top Layer w0.254: U9.19 67.543,76.835 71.784,76.835 C32.2 ; C32.2@71.942,76.962 75.13,76.962 Y1.2
X2: C33.2 RP1.18 U9.18 Y1.1 | length 17.8
  Top Layer w0.254: RP1.18 71.115,72.639 65.888,72.639 U9.18 66.158,72.635 69.146,75.623 C33.2 73.729,75.623 Y1.1
XI: C29.1 U3.7 Y2.2 | length 13.5
  Top Layer w0.254: Y2.2 67.056,9.96 C29.1 68.961,14.097 U3.7
XO: C28.1 U3.8 Y2.1 | length 11.9
  Top Layer w0.254: Y2.1 69.088,10.16 C28.1 69.088,12.954 69.469,13.335 70.993,13.335 71.501,12.827 U3.8
pads on no net: ISP.3 J10.3 J10.5 SK1.1 SK1.4 SK1.5 U1.4 U3.9 U3.10 U3.11 U3.12 U3.13 U3.14 U3.15 U9.29 U9.30 U9.31 USB1.GND

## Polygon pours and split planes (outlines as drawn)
no net on Mechanical 1 "NONET_L01_P-001" (none): 2,0 cw(c2,2) 0,2 0,98 cw(c2,98) 2,100 98,100 cw(c98,98) 100,98 100,2 cw(c98,2) 98,0
GND on Mechanical 1 "NONET_L01_P-001" (none): 2,0 cw(c2,2) 0,2 0,98 cw(c2,98) 2,100 98,100 cw(c98,98) 100,98 100,2 cw(c98,2) 98,0
GND on Top Layer "GND_L01_P011" (solid, remove dead copper, pour order 11): 2,0 cw(c2,2) 0,2 0,98 cw(c2,98) 2,100 98,100 cw(c98,98) 100,98 100,2 cw(c98,2) 98,0
GND on Top Layer "GND_L01_P008" (solid, remove dead copper, pour order 8): 2,0 cw(c2,2) 0,2 0,98 cw(c2,98) 2,100 98,100 cw(c98,98) 100,98 100,2 cw(c98,2) 98,0
GND on Bottom Layer "GND_L02_P009" (solid, remove dead copper, pour order 9): 2,0 cw(c2,2) 0,2 0,98 cw(c2,98) 2,100 98,100 cw(c98,98) 100,98 100,2 cw(c98,2) 98,0

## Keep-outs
Keep-Out Layer:
  lines w0.127: 10.287,0 30.099,0 76.327,0 76.454,0.127 ; 0,2 ccw(c2,2) 2,0 98,0 ccw(c98,2) 100,2 100,98 ccw(c98,98) 98,100 2,100 ccw(c2,98) 0,98 0,2

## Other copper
Top Layer:
  region net VCC: 25.908,47.498 26.162,47.752 27.051,47.752 27.305,47.498 27.305,38.227 27.178,38.1 26.035,38.1 25.908,38.227 25.908,38.481 25.908,38.608 25.908,46.482
  region net NetC37_2: 21.209,13.081 21.971,13.843 21.971,12.827
  region net NetC37_2: 21.789,17.208 21.953,17.399 23.876,17.399 24.13,17.145 24.13,12.573 22.352,12.573 21.789,12.01
  region net NetC37_2: 23.622,13.081 24.13,12.573 24.13,8.509 23.622,8.001 16.256,8.001 14.097,10.16 14.097,12.7 14.478,13.081
  region net NetF1_2: 11.176,11.557 11.43,11.303 12.827,11.303 13.208,11.684 13.208,13.716 13.589,14.097 16.51,14.097 16.764,14.351 16.764,15.621 16.51,15.875 11.303,15.875 11.176,15.748
  region net VCC: 15.367,25.527 15.494,25.654 17.526,25.654 18.796,24.384 19.939,24.384 20.066,24.257 20.066,23.368 19.939,23.241 17.018,23.241 15.875,24.384 15.494,24.384 15.367,24.511

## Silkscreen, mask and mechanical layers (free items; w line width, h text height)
Mechanical 1:
  lines w0.127: 0,2 ccw(c2,2) 2,0 98,0 ccw(c98,2) 100,2 100,98 ccw(c98,98) 98,100 2,100 ccw(c2,98) 0,98 ; 1.778,1.365 1.778,97.365 ; 10.287,0 30.099,0 76.327,0 76.454,0.127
